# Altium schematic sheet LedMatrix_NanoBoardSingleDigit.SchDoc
size A4; Organization: Altium Limited; Address1: L3, 12a Rodborough Rd; Address2: Frenchs Forest; Address3: NSW; Address4: Australia 2086
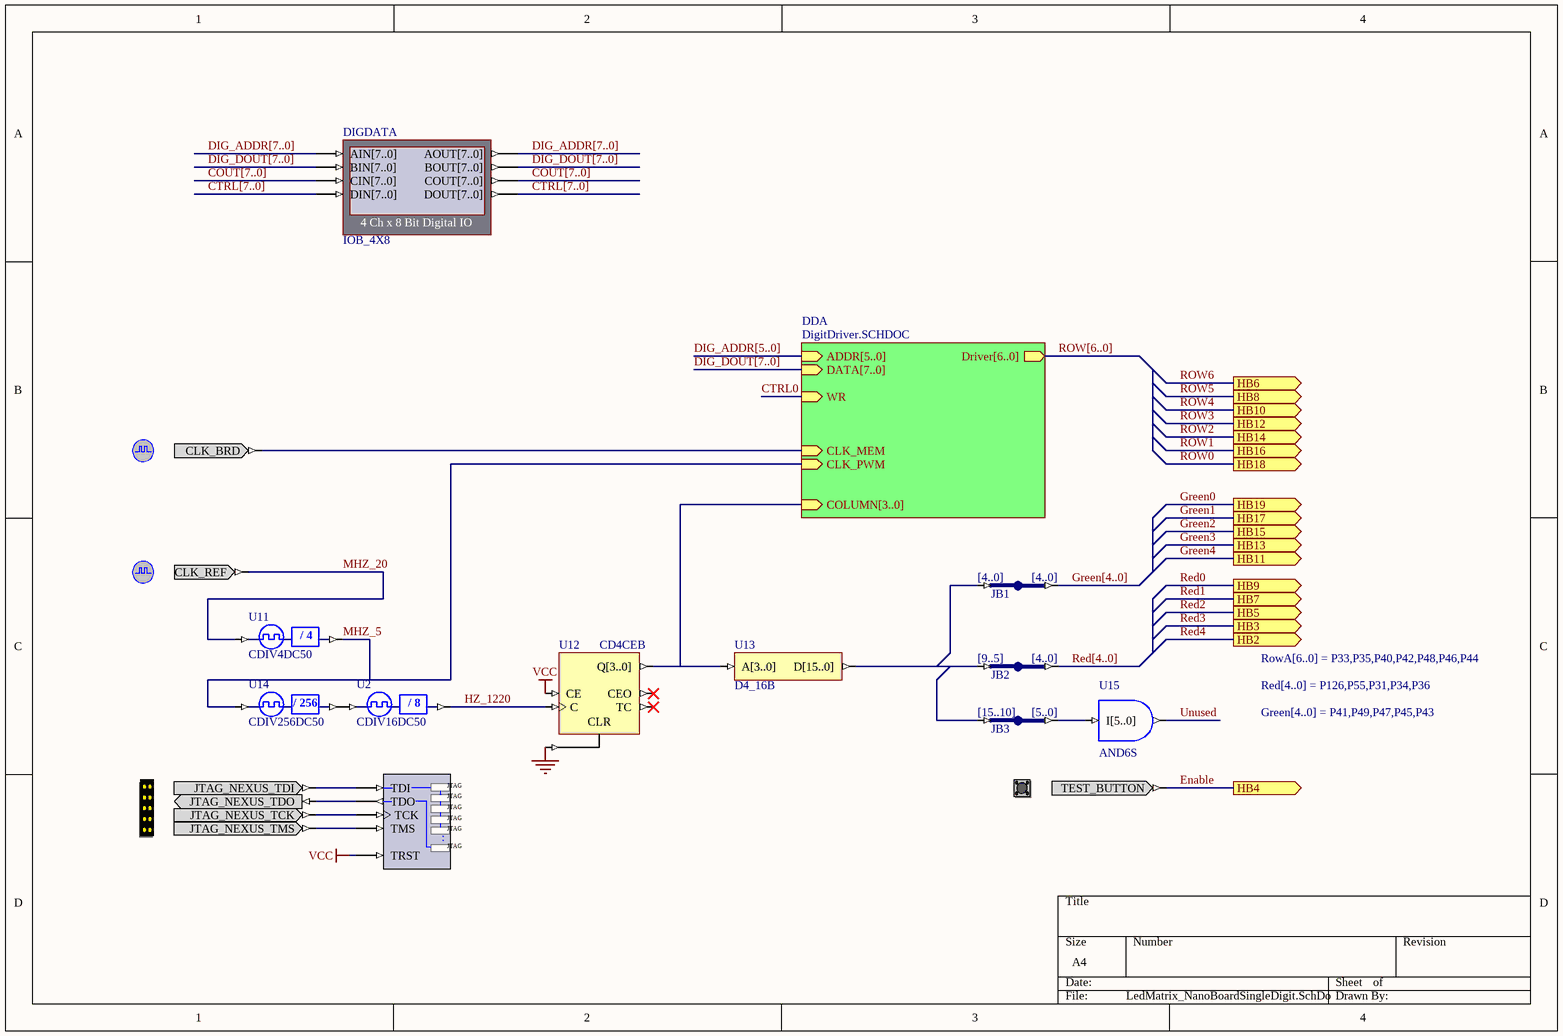
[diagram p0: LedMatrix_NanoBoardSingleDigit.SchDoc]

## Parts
(Parts that share a designator on the sheet are numbered #1, #2 ... from top to bottom, then left to right.)
?#1  CLOCK_BOARD  (value not drawn)
?#2  CLOCK_REFERENCE  (value not drawn)
?#3  NEXUS_JTAG_CONNECTOR  (value not drawn)
?#4  TEST_BUTTON  (value not drawn)
DIGDATA  IOB_4X8
JB1  IndexA: [4..0]  (hidden comment: JB)
JB2  IndexA: [9..5]  IndexB: [4..0]  (hidden comment: JB)
JB3  IndexA: [15..10]  IndexB: [5..0]  (hidden comment: JB)
NEXUS_JTAG_PORT  NEXUS_JTAG_PORT  (value not drawn)
U2  CDIV16DC50
U11  CDIV4DC50
U12  CD4CEB
U13  D4_16B
U14  CDIV256DC50
U15  AND6S

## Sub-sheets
DDA = DigitDriver.SCHDOC: COLUMN[3..0] (in), ADDR[5..0] (in), WR (in), DATA[7..0] (in), CLK_PWM (in), Driver[6..0] (out), CLK_MEM (in)

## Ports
HB2 (out), HB3 (out), HB4 (out), HB5 (out), HB6 (out), HB7 (out), HB8 (out), HB9 (out), HB10 (out), HB11 (out), HB12 (out), HB13 (out), HB14 (out), HB15 (out), HB16 (out), HB17 (out), HB18 (out), HB19 (out)

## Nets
GND: U12.CLR
VCC: NEXUS_JTAG_PORT.TRST U12.CE
Enable: ?#4.TEST_BUTTON ; port HB4
HZ_1220: U2.CLKDV U12.C
MHZ_5: U11.CLKDV U14.CLKIN ; sheet DDA/CLK_PWM
MHZ_20: ?#2.CLK_REF U11.CLKIN
Unused: U15.O
Net?#1_CLK_BRD: ?#1.CLK_BRD ; sheet DDA/CLK_MEM
Net?#3_JTAG_NEXUS_TCK: ?#3.JTAG_NEXUS_TCK NEXUS_JTAG_PORT.TCK
Net?#3_JTAG_NEXUS_TDI: ?#3.JTAG_NEXUS_TDI NEXUS_JTAG_PORT.TDI
Net?#3_JTAG_NEXUS_TDO: ?#3.JTAG_NEXUS_TDO NEXUS_JTAG_PORT.TDO
Net?#3_JTAG_NEXUS_TMS: ?#3.JTAG_NEXUS_TMS NEXUS_JTAG_PORT.TMS
NetU2_CLKIN: U2.CLKIN U14.CLKDV

Not connected (* = marked no-connect by the designer): DIGDATA AIN[7..0] AOUT[7..0] BIN[7..0] BOUT[7..0] CIN[7..0] COUT[7..0] DIN[7..0] DOUT[7..0]; JB1 A[0..0] B[0..0]; JB2 A[0..0] B[0..0]; JB3 A[0..0] B[0..0]; U12 CEO* Q[3..0] TC*; U13 A[3..0] D[15..0]; U15 I[5..0]

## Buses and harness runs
bus COUT[7..0]
bus CTRL[7..0]
bus DIG_ADDR[5..0] = sheet DDA/ADDR[5..0]
bus DIG_ADDR[7..0]
bus DIG_DOUT[7..0]
bus DIG_DOUT[7..0] = sheet DDA/DATA[7..0]
bus Green[4..0]
bus Red[4..0]
bus ROW[6..0] = sheet DDA/Driver[6..0]

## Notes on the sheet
- Red[4..0] = P126,P55,P31,P34,P36
- Green[4..0] = P41,P49,P47,P45,P43
- RowA[6..0] = P33,P35,P40,P42,P48,P46,P44

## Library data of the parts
?#1 = CLOCK_BOARD: Global System Clock Supply; PortComponent: True
?#2 = CLOCK_REFERENCE: Global System Clock Reference Supply; PortComponent: True
?#3 = NEXUS_JTAG_CONNECTOR: JTAG Port; PortComponent: True
?#4 = TEST_BUTTON: Test Button; PortComponent: True
DIGDATA = IOB_4X8: 4 Ch x 8 Bit Digital IO; NEXUS_CORE: Instrument; NEXUS_JTAG_DEVICE: True; NEXUS_JTAG_ORDER: 0
JB1-JB3 = JB: System Joiner; ArchiveName: GENERIC
NEXUS_JTAG_PORT = NEXUS_JTAG_PORT: Soft Nexus-Chain Connector; NEXUS_JTAG_CONNECTOR: True
U2 = CDIV8DC50: Clock Divider by 8 with 50% Duty Cycle Output; ArchiveName: GENERIC; Xilinx Equivalent: CLK_DIV8
U11 = CDIV4DC50: Clock Divider by 4 with 50% Duty Cycle Output; ArchiveName: GENERIC; Xilinx Equivalent: CLK_DIV4
U12 = CD4CEB: 4-Bit Cascadable BCD Counter with Clock Enable and Asynchronous Clear, Bus Version; ArchiveName: GENERIC
U13 = D4_16B: Binary 4- to 16-Bit Decoder, Bus Version; ArchiveName: GENERIC
U14 = CDIV256DC50: Clock Divider by 256 with 50% Duty Cycle Output; ArchiveName: GENERIC
U15 = AND6B: 6-Input AND Gate, Bus Version; ArchiveName: GENERIC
